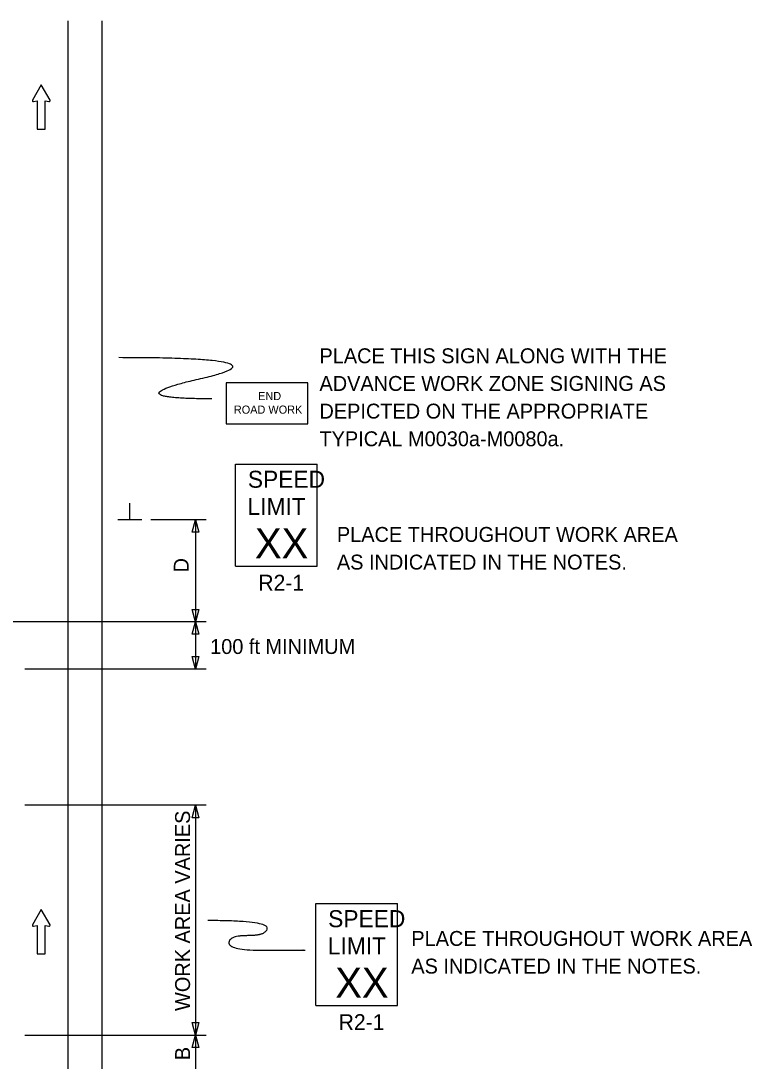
# Model space of a CAD drawing. Extents: x 16740 to 18475, y 5932 to 6927.
# Drawn here: x 17064.1 to 17407.7, y 6427.6 to 6916.5 of the extents above; entities that cross this region are included whole.
import ezdxf

# ---------------------------------------------------------------- set-up
doc = ezdxf.new("R2010")
doc.units = 0
for name, color, linetype in [('MT_SCRATCH_LEVEL_E', 7, 'Continuous'), ('PAVT_EDGE_EX', 7, 'Continuous'), ('TRAFFIC_SIGNS_PR', 7, 'Continuous'), ('TYPICAL_TEXT_DIMEN_PR', 7, 'Continuous')]:
    doc.layers.add(name, color=color, linetype=linetype)

msp = doc.modelspace()

# ---------------------------------------------------------------- linework, layer by layer
at = {"layer": 'MT_SCRATCH_LEVEL_E'}
for p, q in [((17073.64, 6886.4), (17069.53, 6879.15)), ((17073.64, 6886.4), (17069.53, 6879.15)), ((17077.78, 6879.15), (17073.64, 6886.4)), ((17077.78, 6879.15), (17073.64, 6886.4)), ((17070.01, 6878.47), (17071.79, 6878.79)), ((17070.01, 6878.47), (17071.79, 6878.79)), ((17071.79, 6878.79), (17071.79, 6865.53)), ((17071.79, 6878.79), (17071.79, 6865.53)), ((17075.53, 6865.53), (17075.53, 6878.79)), ((17075.53, 6878.79), (17077.3, 6878.47)), ((17075.53, 6865.53), (17075.53, 6878.79)), ((17075.53, 6878.79), (17077.3, 6878.47)), ((17071.79, 6865.53), (17075.53, 6865.53)), ((17071.79, 6865.53), (17075.53, 6865.53)), ((17073.64, 6498.96), (17069.53, 6491.72)), ((17073.64, 6498.96), (17069.53, 6491.72)), ((17077.78, 6491.72), (17073.64, 6498.96)), ((17077.78, 6491.72), (17073.64, 6498.96)), ((17070.01, 6491.04), (17071.79, 6491.35)), ((17070.01, 6491.04), (17071.79, 6491.35)), ((17071.79, 6491.35), (17071.79, 6478.1)), ((17071.79, 6491.35), (17071.79, 6478.1)), ((17075.53, 6478.1), (17075.53, 6491.35)), ((17075.53, 6491.35), (17077.3, 6491.04)), ((17075.53, 6478.1), (17075.53, 6491.35)), ((17075.53, 6491.35), (17077.3, 6491.04)), ((17071.79, 6478.1), (17075.53, 6478.1)), ((17071.79, 6478.1), (17075.53, 6478.1))]:
    msp.add_line(p, q, dxfattribs=at)
for centre, start, end in [((17069.93, 6878.93), 150.4248, 279.9638), ((17069.93, 6878.93), 150.4248, 279.9638), ((17077.37, 6878.93), 260.0362, 29.7731), ((17077.37, 6878.93), 260.0362, 29.7731), ((17069.93, 6491.5), 150.4248, 279.9638), ((17069.93, 6491.5), 150.4248, 279.9638), ((17077.37, 6491.5), 260.0362, 29.7731), ((17077.37, 6491.5), 260.0362, 29.7731)]:
    msp.add_arc(centre, 0.463, start, end, dxfattribs=at)
at = {"layer": 'PAVT_EDGE_EX'}
for p, q in [((17086.12, 6916.46), (17086.12, 6065.34)), ((17102.12, 6916.46), (17102.12, 6065.34))]:
    msp.add_line(p, q, dxfattribs=at)
at = {"layer": 'TRAFFIC_SIGNS_PR'}
for p, q in [((17164.96, 6708.2), (17203.36, 6708.2)), ((17164.96, 6660.2), (17164.96, 6708.2)), ((17203.36, 6660.2), (17203.36, 6708.2)), ((17164.96, 6660.2), (17203.36, 6660.2)), ((17202.7, 6501.73), (17241.1, 6501.73)), ((17202.7, 6453.73), (17202.7, 6501.73)), ((17241.1, 6453.73), (17241.1, 6501.73)), ((17202.7, 6453.73), (17241.1, 6453.73))]:
    msp.add_line(p, q, dxfattribs=at)
msp.add_lwpolyline([(17160.55, 6727.11), (17198.95, 6727.11), (17198.95, 6746.31), (17160.55, 6746.31)], close=True, dxfattribs=at)
msp.add_open_spline([(17153.83, 6738.84), (17106.59, 6738.84), (17191.62, 6758.19), (17110.14, 6758.19)], degree=2, dxfattribs=at)
at = {"layer": 'TYPICAL_TEXT_DIMEN_PR'}
for p, q in [((17115.24, 6682.05), (17115.24, 6689.83)), ((17120.87, 6682.05), (17109.62, 6682.05)), ((17151.12, 6682.05), (17125.12, 6682.05)), ((17144.55, 6676.19), (17146.12, 6682.05)), ((17146.12, 6682.05), (17147.69, 6676.19)), ((17146.12, 6682.05), (17146.12, 6634.06)), ((17146.12, 6676.19), (17144.55, 6676.19)), ((17147.69, 6676.19), (17146.12, 6676.19)), ((17146.12, 6634.06), (17144.55, 6639.93)), ((17144.55, 6639.93), (17146.12, 6639.93)), ((17146.12, 6639.93), (17147.69, 6639.93)), ((17147.69, 6639.93), (17146.12, 6634.06)), ((17151.12, 6634.06), (17041.37, 6634.06)), ((17144.55, 6628.2), (17146.12, 6634.06)), ((17146.12, 6634.06), (17146.12, 6611.86)), ((17146.12, 6634.06), (17147.69, 6628.2)), ((17146.12, 6628.2), (17144.55, 6628.2)), ((17147.69, 6628.2), (17146.12, 6628.2)), ((17146.12, 6611.86), (17144.55, 6617.73)), ((17144.55, 6617.73), (17146.12, 6617.73)), ((17146.12, 6617.73), (17147.69, 6617.73)), ((17147.69, 6617.73), (17146.12, 6611.86)), ((17151.12, 6611.86), (17065.98, 6611.86)), ((17151.12, 6547.86), (17065.98, 6547.86)), ((17144.55, 6542), (17146.12, 6547.86)), ((17146.12, 6547.86), (17146.12, 6439.88)), ((17146.12, 6547.86), (17147.69, 6542)), ((17146.12, 6542), (17144.55, 6542)), ((17147.69, 6542), (17146.12, 6542)), ((17146.12, 6439.88), (17144.55, 6445.74)), ((17144.55, 6445.74), (17146.12, 6445.74)), ((17146.12, 6445.74), (17147.69, 6445.74)), ((17147.69, 6445.74), (17146.12, 6439.88)), ((17065.98, 6439.88), (17151.12, 6439.88)), ((17144.55, 6434.01), (17146.12, 6439.88)), ((17146.12, 6439.88), (17146.12, 6415.88)), ((17146.12, 6439.88), (17147.69, 6434.01)), ((17146.12, 6434.01), (17144.55, 6434.01)), ((17147.69, 6434.01), (17146.12, 6434.01))]:
    msp.add_line(p, q, dxfattribs=at)
msp.add_open_spline([(17151.87, 6493.87), (17179.72, 6493.87), (17179.72, 6486.62), (17161.83, 6486.62), (17161.83, 6479.76), (17194.76, 6479.76), (17197.6, 6479.76)], degree=2, dxfattribs=at)

# ---------------------------------------------------------------- texts
at = {"layer": 'TRAFFIC_SIGNS_PR'}
for s, height, p in [('PLACE THIS SIGN ALONG WITH THE', 7, (17204.38, 6755.57)), ('ADVANCE WORK ZONE SIGNING AS', 7, (17204.38, 6742.57)), ('END', 3.831, (17175.56, 6738.24)), ('DEPICTED ON THE APPROPRIATE', 7, (17204.38, 6729.57)), ('ROAD WORK', 3.831, (17164.16, 6731.85)), ('TYPICAL M0030a-M0080a.', 7, (17204.38, 6716.57)), ('SPEED', 8, (17170.73, 6697.06)), ('LIMIT', 8, (17170.57, 6684.26)), ('XX', 14.031, (17174.08, 6663.95)), ('PLACE THROUGHOUT WORK AREA', 7, (17212.57, 6671.64)), ('AS INDICATED IN THE NOTES.', 7, (17212.57, 6658.64)), ('R2-1', 7.44, (17175.64, 6648.76)), ('SPEED', 8, (17208.47, 6490.6)), ('PLACE THROUGHOUT WORK AREA', 7, (17247.54, 6481.81)), ('LIMIT', 8, (17208.31, 6477.8)), ('AS INDICATED IN THE NOTES.', 7, (17247.54, 6468.81)), ('XX', 14.031, (17211.82, 6457.49)), ('R2-1', 7.44, (17213.38, 6442.29))]:
    msp.add_text(s, height=height, dxfattribs=at).set_placement(p)
at = {"layer": 'TYPICAL_TEXT_DIMEN_PR'}
for s, p in [('D', (17142.92, 6657.27)), ('WORK AREA VARIES', (17143.56, 6451.23)), ('B', (17143.56, 6428.11))]:
    msp.add_text(s, height=7, rotation=90, dxfattribs=at).set_placement(p)
msp.add_text('100 ft MINIMUM', height=7, dxfattribs=at).set_placement((17153.02, 6618.97))

doc.saveas('drawing.dxf')
